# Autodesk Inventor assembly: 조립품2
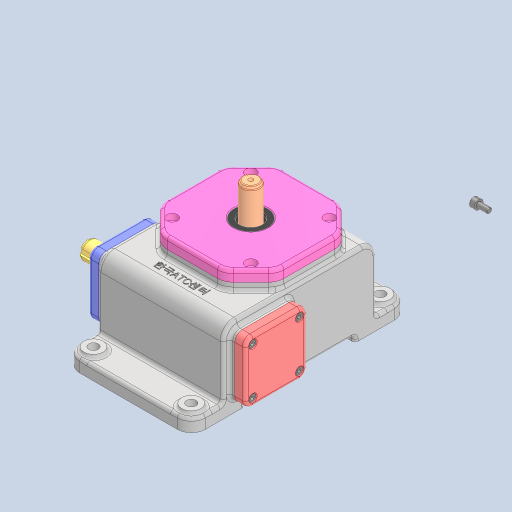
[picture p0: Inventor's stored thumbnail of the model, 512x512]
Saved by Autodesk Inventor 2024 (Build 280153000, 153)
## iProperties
Created: 2026-02
Part Number: 조립품2
Document SubType Name: Assembly
Designer: 2-10
Author: 2-10
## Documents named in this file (14)
- C:\Users\2-10\Desktop\760203V1005\조립품2.iam
- C:\Users\2-10\Desktop\760203V1005\하우징.ipt
- C:\Users\2-10\Desktop\760203V1005\6각 구멍붙이 볼트 M4x10.ipt
- C:\Users\2-10\Desktop\760203V1005\6각 구멍붙이 볼트 M5x10.ipt
- C:\Users\2-10\Desktop\760203V1005\뒷커버.ipt
- C:\Users\2-10\Desktop\760203V1005\앞커버.ipt
- C:\Users\2-10\Desktop\760203V1005\오일 실 17 32 8.ipt
- C:\Users\2-10\Desktop\760203V1005\웜 샤프트.ipt
- C:\Users\2-10\Desktop\760203V1005\웜 휠 커버.ipt
- C:\Users\2-10\Desktop\760203V1005\웜 휠.ipt
- C:\Users\2-10\Desktop\760203V1005\축.ipt
- C:\Users\2-10\Desktop\760203V1005\칼라.ipt
- C:\Users\2-10\Desktop\760203V1005\테이퍼 롤러 베어링 30203.ipt
- C:\Users\2-10\Desktop\760203V1005\평행 키 5x5x16.ipt
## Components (10 placed, 3 different names)
1. 하우징:1
2. 6각 구멍붙이 볼트 M4x10:1
3. 6각 구멍붙이 볼트 M5x10:1
4. 6각 구멍붙이 볼트 M4x10:2
5. 6각 구멍붙이 볼트 M4x10:3
6. 6각 구멍붙이 볼트 M4x10:4
7. 6각 구멍붙이 볼트 M4x10:5
8. 6각 구멍붙이 볼트 M4x10:6
9. 6각 구멍붙이 볼트 M4x10:7
10. 6각 구멍붙이 볼트 M4x10:8
